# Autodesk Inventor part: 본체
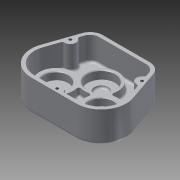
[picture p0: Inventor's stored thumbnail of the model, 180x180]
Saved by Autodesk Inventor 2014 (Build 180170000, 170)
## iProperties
Created: 2014-12
Part Number: 본체
Material: 알루미늄 6061
Document SubType Name: Modeling
Designer: Administrator
Density: 2.71 g/cm^3
Appearance: 알루미늄 - 평지
Mass: 613.37 g
Surface Area: 665.128 cm^2
Volume: 226.336 cm^3
Author: Administrator
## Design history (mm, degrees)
sketch "스케치13"
  geometry: L1 (-34.154, 36)-(34.154, 36); L2 (51.176, 23.851)-(66.009, -19.3); L3 (-51.176, 23.851)-(-66.009, -19.3); L4 (-32.527, -68.527)-(32.527, -68.527); A1 r 36 centre (32.527, -32.527) between (32.527, -68.527) and (66.009, -19.3); A2 r 36 centre (-32.527, -32.527) between (-66.009, -19.3) and (-32.527, -68.527); A3 r 18 centre (-34.154, 18) between (-34.154, 36) and (-51.176, 23.851); A4 r 18 centre (34.154, 18) between (51.176, 23.851) and (34.154, 36)
  constraints: 8 end point, 8 point on circle, 5 tangent, 4 centre point, 1 equal radius
  dimensions: "d55" = 18 radius of A3
extrude "돌출11" new body sketch "스케치13" distance "d56" = 44; taper "d57" = 0 deg
sketch "스케치14"
  geometry: L1 (66.009, -19.3)-(51.176, 23.851) reference; L2 (34.154, 36)-(-34.154, 36) reference; L3 (-51.176, 23.851)-(-66.009, -19.3) reference; L4 (-32.527, -68.527)-(32.527, -68.527) reference; L5 (-34.154, 31)-(34.154, 31); L6 (46.448, 22.226)-(61.319, -21.036); L7 (32.527, -63.527)-(-32.527, -63.527); L8 (-61.319, -21.036)-(-46.448, 22.226); A1 r 18 centre (34.154, 18) between (51.176, 23.851) and (34.154, 36) reference; A2 r 18 centre (-34.154, 18) between (-34.154, 36) and (-51.176, 23.851) reference; A3 r 36 centre (-32.527, -32.527) between (-66.009, -19.3) and (-32.527, -68.527) reference; A4 r 36 centre (32.527, -32.527) between (32.527, -68.527) and (66.009, -19.3) reference; A5 r 13 centre (34.154, 18) between (46.448, 22.226) and (34.154, 31); A6 r 31 centre (32.527, -32.527) between (32.527, -63.527) and (61.319, -21.036); A7 r 31 centre (-32.527, -32.527) between (-61.319, -21.036) and (-32.527, -63.527); A8 r 13 centre (-34.154, 18) between (-34.154, 31) and (-46.448, 22.226); 1 further point
  constraints: 8 end point, 8 point on circle, 4 centre point, 7 other
  dimensions: "d58" = 5 distance between parallel lines of L5 L2
extrude "돌출12" cut sketch "스케치14" distance "d59" = 34; taper "d60" = 0 deg
sketch "스케치15"
  geometry: C1 r 24 at (0, 0); C2 r 24 at (32.527, -32.527); C3 r 24 at (-32.527, -32.527); A1 r 31 centre (-32.527, -32.527) between (-61.319, -21.036) and (-32.527, -63.527) reference; A2 r 31 centre (32.527, -32.527) between (32.527, -63.527) and (61.319, -21.036) reference; 1 further point
  constraints: 3 centre point, 3 coincident
  dimensions: "d61" = 48 diameter of C1; "d62" = 48 diameter of C2; "d63" = 48 diameter of C3
extrude "돌출13" join sketch "스케치15" distance "d64" = 11; taper "d65" = 0 deg
sketch "스케치16"
  geometry: C1 r 20 at (0, 0); A1 r 24 centre (0, 0) between (-11.416, -21.111) and (11.416, -21.111) reference
  constraints: 1 centre point, 1 coincident
  dimensions: "d66" = 40 diameter of C1
extrude "돌출14" cut sketch "스케치16" distance "d67" = 12; taper "d68" = 0 deg
sketch "스케치17"
  geometry: C1 r 17.5 at (-32.527, -32.527); C2 r 17.5 at (32.527, -32.527); A1 r 24 centre (-32.527, -32.527) between (-21.111, -11.416) and (-11.416, -21.111) reference; A2 r 24 centre (32.527, -32.527) between (11.416, -21.111) and (21.111, -11.416) reference
  constraints: 2 centre point, 2 coincident
  dimensions: "d69" = 35 diameter of C1; "d70" = 35 diameter of C2
extrude "돌출15" cut sketch "스케치17" distance "d71" = 11; taper "d72" = 0 deg
sketch "스케치18"
  geometry: C1 r 20 at (-32.527, -32.527); C2 r 20 at (32.527, -32.527); A1 r 36 centre (-32.527, -32.527) between (-66.009, -19.3) and (-32.527, -68.527) reference; A2 r 36 centre (32.527, -32.527) between (32.527, -68.527) and (66.009, -19.3) reference; 1 further point
  constraints: 2 centre point, 2 coincident
  dimensions: "d73" = 40 diameter of C1; "d74" = 40 diameter of C2
extrude "돌출16" join sketch "스케치18" distance "d75" = 7; taper "d76" = -10 deg
sketch "스케치19"
  geometry: C1 r 18.766 at (0, 0) reference; C2 r 18.766 at (65.054, 0) reference; C3 r 15 at (0, 0); C4 r 15 at (65.054, 0); 1 further point
  constraints: 2 centre point, 2 coincident
  dimensions: "d77" = 30 diameter of C3; "d78" = 30 diameter of C4
extrude "돌출17" cut sketch "스케치19" distance "d79" = 7; taper "d80" = 0 deg
sketch "스케치20"
  geometry: C1 r 15 at (0, 0) reference; C2 r 15 at (65.054, 0) reference; C3 r 7.75 at (0, 0); C4 r 7.75 at (65.054, 0); 1 further point
  constraints: 2 centre point, 2 coincident
  dimensions: "d81" = 15.5 diameter of C3; "d82" = 15.5 diameter of C4
extrude "돌출18" cut sketch "스케치20" distance "d83" = 10; taper "d84" = 0 deg
sketch "스케치21"
  geometry: L1 (34.154, 36)-(-34.154, 36) reference; L2 (46.448, 22.226)-(61.319, -21.036) reference; L3 (32.527, -63.527)-(-32.527, -63.527) reference; L4 (-8, -63.527)-(8, -63.527); L5 (49.081, 14.566)-(54.282, -0.566); L6 (-49.081, 14.566)-(-54.282, -0.566); A1 r 13 centre (34.154, 18) between (46.448, 22.226) and (34.154, 31) reference; A2 r 8 centre (51.681, 7) between (49.081, 14.566) and (54.282, -0.566); A3 r 8 centre (0, -63.527) between (8, -63.527) and (-8, -63.527); A4 r 8 centre (-51.681, 7) between (-54.282, -0.566) and (-49.081, 14.566)
  constraints: 6 end point, 6 point on circle, 4 point on line, 3 centre point, 2 collinear, 1 midpoint
  dimensions: "d86" = 16 diameter of A2; "d87" = 16 diameter of A3
extrude "돌출19" join sketch "스케치21" stored distance "d88" = 10; taper "d89" = 0 deg
sketch "스케치22"
  geometry: C1 r 5.393 at (-51.681, 7); C2 r 5.987 at (51.681, 7); C3 r 3.847 at (0, -63.527); A1 r 8 centre (51.681, 7) between (49.081, 14.566) and (54.282, -0.566) reference; A2 r 8 centre (0, -63.527) between (8, -63.527) and (-8, -63.527) reference; A3 r 8 centre (-51.681, 7) between (-54.282, -0.566) and (-49.081, 14.566) reference; 1 further point
  constraints: 3 centre point, 3 coincident
hole "구멍1" sketch "스케치22" at (-51.681, 7), (51.681, 7), (0, -63.527) diameter "d90" = 4.134; stored, may be unused: countersink angle "d94" = 90 deg, drill point angle "d96" = 118 deg; dims "d91" = 20, "d92" = 4, "d93" = 2, "d95" = 23
sketch "스케치23"
  geometry: L1 (-34.154, 36)-(34.154, 36) reference; L2 (0, 36)-(0, 6); L3 (-24.638, 9.465)-(25.137, 9.465); L4 (25.137, 9.465)-(25.137, 2.26); L5 (25.137, 2.26)-(-24.638, 2.26); L6 (-24.638, 2.26)-(-24.638, 9.465); 1 further point
  constraints: 2 end point, 1 midpoint, 1 perpendicular, 2 other
  dimensions: "d97" = 30 distance of L2.start L2.end
feature "엠보싱1" sketch "스케치23" dims "d55" = 18, "d98" = 1, "d99" = 0
fillet "모깎기1" dims "d100" = 3
fillet "모깎기2" dims "d101" = 3
sketch "스케치24"
  geometry: C1 r 20 at (0, 0) reference; C2 r 10 at (0, 0)
  constraints: 1 centre point, 1 coincident
  dimensions: "d102" = 20 diameter of C2
extrude "돌출20" cut sketch "스케치24" distance "d103" = 3; taper "d104" = 0 deg
fillet "모깎기3" dims "d105" = 3
fillet "모깎기4" dims "d106" = 3
fillet "모깎기5" dims "d107" = 3
fillet "모깎기6" dims "d108" = 3
chamfer "모따기1" distance "d109" = 1; stored, may be unused: second distance "d110" = 2, angle "d111" = 45 deg
fillet "모깎기7" dims "d112" = 0.3
fillet "모깎기8" dims "d113" = 3
chamfer "모따기2" distance "d114" = 1; stored, may be unused: second distance "d115" = 2, angle "d116" = 45 deg
chamfer "모따기3" distance "d117" = 1; stored, may be unused: second distance "d118" = 2, angle "d119" = 45 deg
fillet "모깎기9" dims "d120" = 0.1
node "솔리드2"
node "투영된 루프4"
node "투영된 루프5"
other parameters: "d8" = 72, "d51" = 72
